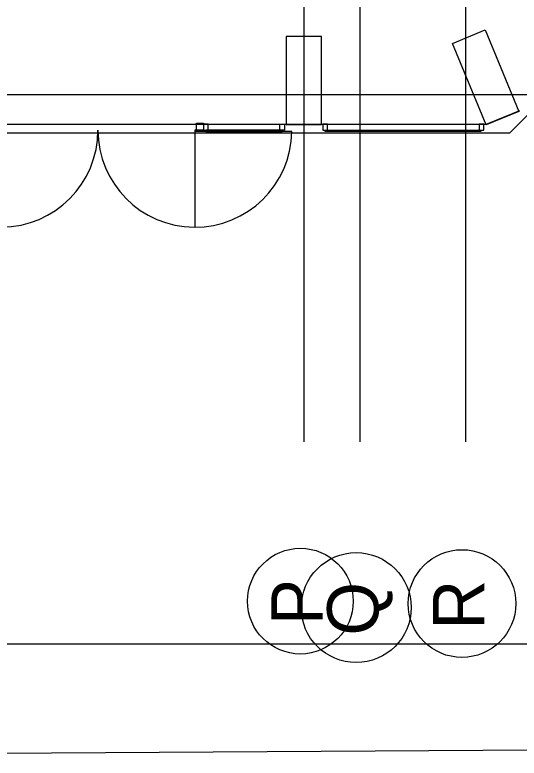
# Model space of a CAD drawing. Extents: x -264031 to -263588, y -1242281 to -1242059.
# Drawn here: x -263817.39 to -263808.81, y -1242252.09 to -1242239.45 of the extents above; entities that cross this region are included whole.
import ezdxf

# ---------------------------------------------------------------- set-up
doc = ezdxf.new("R2010")
doc.units = 0
for name, color, linetype in [('HESCON_OSI_STAVBY_KFA', 7, 'Continuous'), ('KFA_2D_SITUACIA_DSP', 7, 'Continuous'), ('KFA_JESTV_IS_DSP_-_KANAL_SPLASK', 7, 'Continuous')]:
    doc.layers.add(name, color=color, linetype=linetype)

msp = doc.modelspace()

# ---------------------------------------------------------------- linework, layer by layer
at = {"layer": 'HESCON_OSI_STAVBY_KFA'}
for p, q in [((-263812.468, -1242083.237), (-263812.468, -1242246.707)), ((-263811.518, -1242083.237), (-263811.518, -1242246.707)), ((-263809.718, -1242083.237), (-263809.718, -1242246.707)), ((-263792.653, -1242240.807), (-263911.523, -1242240.807))]:
    msp.add_line(p, q, dxfattribs=at)
for centre, radius in [((-263812.528, -1242249.416), 0.899), ((-263811.578, -1242249.526), 0.935), ((-263809.778, -1242249.457), 0.916)]:
    msp.add_circle(centre, radius, dxfattribs=at)
at = {"layer": 'KFA_2D_SITUACIA_DSP'}
for p, q in [((-263809.939, -1242239.932), (-263809.384, -1242239.702)), ((-263809.384, -1242239.702), (-263808.81, -1242241.088)), ((-263812.768, -1242239.812), (-263812.768, -1242241.312)), ((-263812.168, -1242239.812), (-263812.768, -1242239.812)), ((-263812.168, -1242241.312), (-263812.168, -1242239.812)), ((-263809.365, -1242241.318), (-263809.939, -1242239.932)), ((-263808.81, -1242241.088), (-263809.365, -1242241.318)), ((-263808.8, -1242241.078), (-263809.355, -1242241.307)), ((-263894.581, -1242241.307), (-263809.355, -1242241.307)), ((-263814.298, -1242241.407), (-263814.298, -1242241.287)), ((-263814.298, -1242241.287), (-263814.178, -1242241.287)), ((-263814.178, -1242241.287), (-263814.178, -1242241.407)), ((-263814.098, -1242241.307), (-263814.178, -1242241.307)), ((-263814.178, -1242241.307), (-263814.178, -1242241.407)), ((-263814.098, -1242241.407), (-263814.098, -1242241.307)), ((-263812.878, -1242241.407), (-263812.878, -1242241.307)), ((-263812.878, -1242241.307), (-263812.798, -1242241.307)), ((-263812.798, -1242241.307), (-263812.798, -1242241.407)), ((-263812.768, -1242241.312), (-263812.168, -1242241.312)), ((-263812.068, -1242241.307), (-263812.148, -1242241.307)), ((-263812.148, -1242241.307), (-263812.148, -1242241.407)), ((-263812.068, -1242241.407), (-263812.068, -1242241.307)), ((-263809.405, -1242241.307), (-263809.485, -1242241.307)), ((-263809.485, -1242241.307), (-263809.485, -1242241.407)), ((-263809.405, -1242241.407), (-263809.405, -1242241.307)), ((-263814.298, -1242241.407), (-263814.323, -1242241.407)), ((-263814.323, -1242241.407), (-263814.323, -1242243.057)), ((-263812.673, -1242241.432), (-263814.323, -1242241.432)), ((-263814.178, -1242241.407), (-263814.298, -1242241.407)), ((-263814.178, -1242241.407), (-263814.138, -1242241.407)), ((-263812.838, -1242241.407), (-263814.138, -1242241.407)), ((-263814.138, -1242241.407), (-263814.138, -1242241.432)), ((-263814.138, -1242241.407), (-263814.098, -1242241.407)), ((-263814.138, -1242241.432), (-263812.838, -1242241.432)), ((-263812.838, -1242241.407), (-263812.878, -1242241.407)), ((-263812.838, -1242241.432), (-263812.838, -1242241.407)), ((-263812.798, -1242241.407), (-263812.838, -1242241.407)), ((-263812.148, -1242241.407), (-263812.108, -1242241.407)), ((-263812.108, -1242241.432), (-263812.108, -1242241.407)), ((-263812.108, -1242241.407), (-263809.458, -1242241.407)), ((-263812.108, -1242241.407), (-263812.068, -1242241.407)), ((-263809.458, -1242241.432), (-263812.108, -1242241.432)), ((-263809.485, -1242241.407), (-263809.445, -1242241.407)), ((-263809.458, -1242241.407), (-263809.458, -1242241.432)), ((-263809.445, -1242241.407), (-263809.405, -1242241.407)), ((-263924.143, -1242250.14), (-263788.143, -1242250.14))]:
    msp.add_line(p, q, dxfattribs=at)
msp.add_lwpolyline([(-263794.893, -1242227.382), (-263808.968, -1242241.457), (-263894.968, -1242241.457), (-263909.043, -1242227.382), (-263909.043, -1242196.333), (-263914.143, -1242196.333), (-263914.143, -1242132.433), (-263909.043, -1242132.433), (-263909.043, -1242101.382), (-263894.968, -1242087.307), (-263808.968, -1242087.307), (-263794.893, -1242101.382), (-263794.893, -1242227.382)], dxfattribs=at)
for centre, start, end in [((-263817.623, -1242241.407), 180.8682, 0), ((-263814.323, -1242241.407), 180, 359.1318)]:
    msp.add_arc(centre, 1.65, start, end, dxfattribs=at)
at = {"layer": 'KFA_JESTV_IS_DSP_-_KANAL_SPLASK'}
msp.add_line((-263792.798, -1242251.862), (-263831.703, -1242252.086), dxfattribs=at)

# ---------------------------------------------------------------- texts
at = {"layer": 'HESCON_OSI_STAVBY_KFA'}
for s, p in [('P', (-263812.147, -1242249.824)), ('Q', (-263811.197, -1242250.001)), ('R', (-263809.397, -1242249.898))]:
    msp.add_text(s, height=0.875, rotation=90, dxfattribs=at).set_placement(p)

doc.saveas('drawing.dxf')
